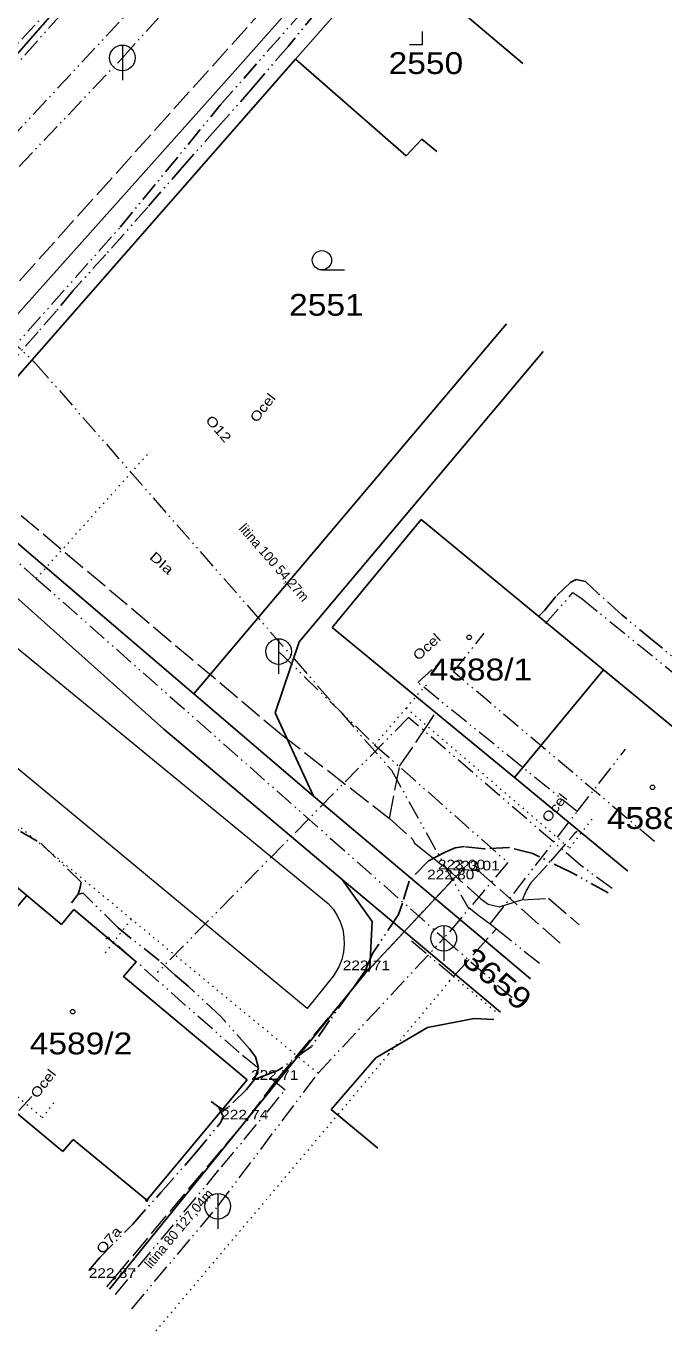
# Model space of a CAD drawing. Extents: x -683947 to -683762, y -1065756 to -1065543.
# Drawn here: x -683884.2 to -683834.4, y -1065755.7 to -1065654 of the extents above; entities that cross this region are included whole.
import ezdxf
from ezdxf.enums import TextEntityAlignment as Align

# ---------------------------------------------------------------- set-up
doc = ezdxf.new("R2010")
doc.units = 0
doc.header["$LTSCALE"] = 0.3
doc.header["$PDMODE"] = 32
doc.header["$PDSIZE"] = 0.15
for name, pattern in [('DASH_DOUBLE_DOT', [9.2, 5, -1.2, 0.3, -1.2, 0.3, -1.2]), ('DOTTED', [1.5, 0.3, -1.2]), ('LONG_DASHED', [7.5, 6, -1.5])]:
    doc.linetypes.add(name, pattern=pattern)
for name, color, linetype, lineweight in [('1', 7, 'Continuous', 25), ('10', 7, 'Continuous', 13), ('25', 7, 'Continuous', 13), ('3', 7, 'Continuous', 13), ('30', 7, 'LONG_DASHED', 13), ('31', 7, 'DASH_DOUBLE_DOT', 13), ('35', 7, 'LONG_DASHED', 13), ('36', 7, 'DASH_DOUBLE_DOT', 25), ('4', 7, 'Continuous', 13), ('41', 7, 'DASH_DOUBLE_DOT', 13), ('46', 7, 'DASH_DOUBLE_DOT', 13), ('5', 7, 'Continuous', 13), ('50', 7, 'LONG_DASHED', 13), ('51', 7, 'DOTTED', 13)]:
    doc.layers.add(name, color=color, linetype=linetype, lineweight=lineweight)
for name, color, linetype in [('15', 7, 'Continuous'), ('16', 7, 'Continuous'), ('19', 7, 'Continuous'), ('2', 7, 'Continuous')]:
    doc.layers.add(name, color=color, linetype=linetype)

msp = doc.modelspace()

# ---------------------------------------------------------------- linework, layer by layer
at = {"layer": '1'}
for p, q in [((-683867.65, -1065657.22), (-683844.35, -1065631.04)), ((-683863.13, -1065656.59), (-683855.75, -1065648.18)), ((-683845.419, -1065656.92), (-683855.75, -1065648.18)), ((-683888.65, -1065685.67), (-683863.13, -1065656.59)), ((-683863.13, -1065656.59), (-683854.52, -1065664.13)), ((-683886.11, -1065677.9), (-683867.65, -1065657.22)), ((-683854.52, -1065664.13), (-683853.28, -1065662.81)), ((-683853.28, -1065662.81), (-683852.122, -1065663.784)), ((-683846.693, -1065677.227), (-683871.07, -1065706.07)), ((-683843.823, -1065679.379), (-683862.85, -1065702.02)), ((-683886.97, -1065692.49), (-683871.07, -1065706.07)), ((-683860.28, -1065700.9), (-683853.33, -1065692.48)), ((-683853.33, -1065692.48), (-683839.13, -1065704.18)), ((-683890.08, -1065693.94), (-683873.4, -1065708.83)), ((-683846.07, -1065712.6), (-683860.28, -1065700.9)), ((-683862.85, -1065702.02), (-683864.72, -1065707.54)), ((-683846.07, -1065712.6), (-683839.13, -1065704.18)), ((-683839.13, -1065704.18), (-683829.912, -1065711.781)), ((-683871.07, -1065706.07), (-683861.75, -1065714.03)), ((-683864.72, -1065707.54), (-683861.75, -1065714.03)), ((-683873.4, -1065708.83), (-683859.51, -1065720.53)), ((-683837.223, -1065719.883), (-683846.07, -1065712.6)), ((-683861.75, -1065714.03), (-683844.81, -1065728.29)), ((-683859.51, -1065720.53), (-683847.158, -1065730.892)), ((-683884.1, -1065721.78), (-683881.4, -1065724.04)), ((-683880.43, -1065722.89), (-683881.4, -1065724.04)), ((-683857.34, -1065727.39), (-683877.651, -1065752.468)), ((-683852.84, -1065732.07), (-683849.22, -1065731.37)), ((-683849.22, -1065731.37), (-683847.665, -1065731.453)), ((-683881.3, -1065741.76), (-683892.92, -1065732.04)), ((-683856.88, -1065734.45), (-683852.84, -1065732.07)), ((-683860.35, -1065738.48), (-683856.88, -1065734.45)), ((-683866.92, -1065736.17), (-683874.74, -1065745.55)), ((-683860.35, -1065738.48), (-683856.71, -1065741.477)), ((-683880.49, -1065740.8), (-683881.3, -1065741.76)), ((-683874.74, -1065745.55), (-683880.49, -1065740.8))]:
    msp.add_line(p, q, dxfattribs=at)
for points in [[(-683859.58, -1065630.9), (-683875.3, -1065645.28), (-683888.43, -1065660.25), (-683897.91, -1065674.98), (-683898.51, -1065675.59)], [(-683890.26, -1065716.63), (-683884.1, -1065721.78), (-683892.92, -1065732.04)], [(-683859.51, -1065720.53), (-683857.17, -1065723.82), (-683857.34, -1065727.39)], [(-683866.92, -1065736.17), (-683876.55, -1065728.11), (-683875.58, -1065726.95), (-683880.43, -1065722.89)]]:
    msp.add_lwpolyline(points, dxfattribs=at)
for p in [(-683850.03, -1065719.75), (-683848.89, -1065719.83), (-683850.87, -1065720.53), (-683857.45, -1065727.61), (-683864.6, -1065736.16), (-683866.93, -1065739.25), (-683874.73, -1065745.55), (-683877.26, -1065751.6)]:
    msp.add_point(p, dxfattribs=at)
at = {"layer": '10'}
for p, q in [((-683876.643, -1065655.478), (-683876.643, -1065658.226)), ((-683864.461, -1065701.762), (-683864.461, -1065704.51)), ((-683851.577, -1065724.123), (-683851.577, -1065726.871)), ((-683869.206, -1065745.016), (-683869.206, -1065747.764))]:
    msp.add_line(p, q, dxfattribs=at)
for centre in [(-683876.643, -1065656.48), (-683864.461, -1065702.764), (-683851.577, -1065725.125), (-683869.206, -1065746.018)]:
    msp.add_circle(centre, 1, dxfattribs=at)
at = {"layer": '25'}
msp.add_line((-683850.884, -1065720.557), (-683857.417, -1065727.554), dxfattribs=at)
at = {"layer": '3'}
msp.add_line((-683861.082, -1065673.01), (-683859.332, -1065673.01), dxfattribs=at)
msp.add_lwpolyline([(-683854.24, -1065655.43), (-683853.24, -1065655.43), (-683853.24, -1065654.43)], dxfattribs=at)
msp.add_circle((-683861.082, -1065672.26), 0.75, dxfattribs=at)
at = {"layer": '30'}
msp.add_lwpolyline([(-683877.845, -1065752.294), (-683877.26, -1065751.6), (-683866.93, -1065739.25), (-683864.6, -1065736.16), (-683857.45, -1065727.61), (-683850.87, -1065720.53), (-683850.03, -1065719.75), (-683848.89, -1065719.83), (-683842.386, -1065725.603)], dxfattribs=at)
at = {"layer": '31'}
for points in [[(-683906.37, -1065683.43), (-683899.08, -1065675.36), (-683887.96, -1065660.41), (-683873.71, -1065644.44), (-683851.65, -1065622.08)], [(-683914.84, -1065689.19), (-683909.62, -1065682.86), (-683896.8, -1065669.54), (-683888.32, -1065659.06), (-683854.06, -1065622.89)], [(-683843.64, -1065700.59), (-683841.5, -1065698.17), (-683840.79, -1065698.66), (-683827.681, -1065709.309)], [(-683835.143, -1065717.578), (-683850.82, -1065704.35), (-683848.42, -1065701.33)], [(-683867.54, -1065734.03), (-683877.74, -1065725.03), (-683877.93, -1065725.19)], [(-683877.188, -1065752.885), (-683868.91, -1065742.95), (-683863.95, -1065736.96), (-683867.54, -1065734.03)]]:
    msp.add_lwpolyline(points, dxfattribs=at)
at = {"layer": '35'}
msp.add_line((-683850.814, -1065728.102), (-683847.469, -1065724.389), dxfattribs=at)
for points in [[(-683896.24, -1065687.55), (-683894.71, -1065685.72), (-683893.48, -1065684.13), (-683891.61, -1065681.955), (-683887.89, -1065677.63), (-683886.16, -1065675.53), (-683853.44, -1065639.1), (-683848.45, -1065633.59), (-683843.114, -1065627.22), (-683843.08, -1065627.18), (-683831.4, -1065614.21), (-683820.06, -1065601.41), (-683812.91, -1065593.55), (-683807.75, -1065587.62), (-683793.84, -1065572.21), (-683791.969, -1065570.179), (-683790.708, -1065568.809), (-683790.074, -1065568.129)], [(-683887.28, -1065689.61), (-683886.26, -1065690.7), (-683864.21, -1065709.26), (-683855.82, -1065715.78), (-683853.98, -1065717.41), (-683853.87, -1065717.71), (-683852.4, -1065718.86), (-683851.92, -1065719.26), (-683851.43, -1065719.6), (-683848.68, -1065722.04), (-683848.11, -1065722.47), (-683847.23, -1065722.66), (-683845.45, -1065722.12), (-683843.4, -1065722), (-683841.012, -1065724.081)]]:
    msp.add_lwpolyline(points, dxfattribs=at)
at = {"layer": '36', "lineweight": 13}
for p, q in [((-683891.662, -1065672.348), (-683883.388, -1065680.331)), ((-683847.469, -1065724.389), (-683843.876, -1065727.255)), ((-683850.814, -1065728.102), (-683854.244, -1065725.23))]:
    msp.add_line(p, q, dxfattribs=at)
at = {"layer": '36'}
for p, q in [((-683880.1, -1065721.68), (-683880.61, -1065722.37)), ((-683869.11, -1065738.29), (-683869.73, -1065737.86))]:
    msp.add_line(p, q, dxfattribs=at)
at = {"layer": '36', "linetype": 'DOTTED', "lineweight": 13}
for p, q in [((-683851.132, -1065728.477), (-683850.814, -1065728.102)), ((-683850.814, -1065728.102), (-683847.287, -1065731.035))]:
    msp.add_line(p, q, dxfattribs=at)
at = {"layer": '36', "lineweight": 13}
for points in [[(-683893.079, -1065671.05), (-683871.468, -1065647.886), (-683863.976, -1065639.798), (-683853.405, -1065628.437)], [(-683883.388, -1065680.331), (-683855.658, -1065712.024), (-683849.733, -1065722.644)], [(-683849.733, -1065722.644), (-683848.854, -1065723.341), (-683847.96, -1065723.998), (-683847.469, -1065724.389)]]:
    msp.add_lwpolyline(points, dxfattribs=at)
at = {"layer": '36'}
for points in [[(-683861.4, -1065652.77), (-683863.72, -1065655.58), (-683866.45, -1065658.77), (-683869.22, -1065661.92), (-683871.81, -1065664.82), (-683874.67, -1065668.11), (-683877.93, -1065671.8), (-683880.49, -1065674.63), (-683881.78, -1065676.2), (-683883.21, -1065677.83), (-683885.92, -1065680.91), (-683888.71, -1065684.04), (-683891.65, -1065687.67), (-683894.43, -1065691.13), (-683895.32, -1065692.06), (-683895.79, -1065692.2), (-683896.27, -1065692.12), (-683897.08, -1065691.84)], [(-683828.07, -1065708.5), (-683828.11, -1065707.94), (-683829.41, -1065706.7), (-683832.38, -1065704.28), (-683835.16, -1065701.99), (-683837.7, -1065699.9), (-683839.54, -1065698.24), (-683840.53, -1065697.3), (-683841.24, -1065697.16), (-683841.68, -1065697.36), (-683842.84, -1065698.47), (-683843.7, -1065699.53), (-683844.21, -1065700.05)], [(-683894.53, -1065710.88), (-683894.11, -1065710.62), (-683893.72, -1065710.81), (-683891.9, -1065711.74), (-683890.27, -1065713.01), (-683886.64, -1065715.22), (-683884.59, -1065716.8), (-683882.93, -1065717.78), (-683879.86, -1065720.75), (-683879.93, -1065721.17), (-683880.1, -1065721.68)], [(-683838.762, -1065721.588), (-683841.61, -1065719.99), (-683844.64, -1065718.52), (-683846.48, -1065718.05), (-683848.39, -1065718.14), (-683849.95, -1065717.98), (-683850.7, -1065718.07), (-683851.47, -1065718.41), (-683852.76, -1065719.08), (-683854.29, -1065720.66), (-683854.8, -1065722.38), (-683855.11, -1065723.27), (-683857.13, -1065726.3), (-683857.72, -1065727.65), (-683858.93, -1065729.38), (-683860.49, -1065731.54), (-683861.89, -1065733.55), (-683864.46, -1065735.41), (-683865.62, -1065735.84), (-683866.33, -1065736.13)], [(-683866.33, -1065736.13), (-683866.03, -1065735.22), (-683866.26, -1065734.36), (-683866.72, -1065733.75), (-683868.98, -1065731.2), (-683871.51, -1065728.86), (-683872.53, -1065728), (-683873.78, -1065726.86), (-683876.98, -1065724.31), (-683879.7, -1065721.61), (-683880.1, -1065721.68)], [(-683866.33, -1065736.13), (-683866.96, -1065736.91), (-683868.4, -1065738.31), (-683868.74, -1065738.49), (-683869.11, -1065738.29)], [(-683879.254, -1065751.024), (-683878.43, -1065750.05), (-683875.83, -1065747.4), (-683873.61, -1065744.92), (-683871.02, -1065741.96), (-683868.99, -1065739.5), (-683868.78, -1065739.02), (-683869.11, -1065738.29)]]:
    msp.add_lwpolyline(points, dxfattribs=at)
at = {"layer": '36', "linetype": 'DOTTED', "lineweight": 13}
msp.add_lwpolyline([(-683874.022, -1065755.735), (-683855.873, -1065734.165), (-683851.132, -1065728.477)], dxfattribs=at)
at = {"layer": '4'}
for p, q in [((-683892.15, -1065696.52), (-683860.6, -1065722.41)), ((-683862.22, -1065730.6), (-683896.78, -1065702.01)), ((-683860.18, -1065728.05), (-683862.22, -1065730.6))]:
    msp.add_line(p, q, dxfattribs=at)
msp.add_lwpolyline([(-683860.6, -1065722.41), (-683860.21, -1065722.86), (-683859.89, -1065723.35), (-683859.64, -1065723.89), (-683859.46, -1065724.45), (-683859.36, -1065725.03), (-683859.34, -1065725.62), (-683859.4, -1065726.21), (-683859.54, -1065726.79), (-683859.76, -1065727.34), (-683860.18, -1065728.05)], dxfattribs=at)
at = {"layer": '41'}
for p, q in [((-683838.455, -1065721.248), (-683840.889, -1065719.446)), ((-683883.719, -1065737.449), (-683888.487, -1065742.712))]:
    msp.add_line(p, q, dxfattribs=at)
at = {"layer": '41', "lineweight": 25}
msp.add_lwpolyline([(-683907.26, -1065705.67), (-683893.37, -1065687.98), (-683887.71, -1065681.96), (-683876.81, -1065669.67), (-683869.01, -1065660.17), (-683861.43, -1065651.54), (-683852.89, -1065642.04), (-683845.02, -1065633.03), (-683836.31, -1065623.45), (-683820.34, -1065605.7), (-683789.54, -1065571.05), (-683781.76, -1065562.31), (-683777.124, -1065557.504)], dxfattribs=at)
at = {"layer": '41'}
msp.add_lwpolyline([(-683840.889, -1065719.446), (-683854.319, -1065707.903), (-683873.919, -1065727.794)], dxfattribs=at)
at = {"layer": '46'}
for p, q in [((-683876.643, -1065656.48), (-683852.585, -1065629.704)), ((-683864.461, -1065702.764), (-683856.969, -1065710.032)), ((-683851.577, -1065725.125), (-683846.179, -1065729.807)), ((-683875.92, -1065754.026), (-683869.206, -1065746.018))]:
    msp.add_line(p, q, dxfattribs=at)
for points in [[(-683899.015, -1065681.258), (-683890.444, -1065670.977), (-683876.643, -1065656.48)], [(-683896.766, -1065685.158), (-683883.356, -1065697.074), (-683851.577, -1065725.125)], [(-683856.969, -1065710.032), (-683846.574, -1065719.227), (-683851.577, -1065725.125)], [(-683869.206, -1065746.018), (-683861.384, -1065735.651), (-683851.577, -1065725.125)]]:
    msp.add_lwpolyline(points, dxfattribs=at)
at = {"layer": '5'}
for centre in [(-683849.597, -1065701.659), (-683835.297, -1065713.349), (-683880.517, -1065730.849)]:
    msp.add_circle(centre, 0.175, dxfattribs=at)
at = {"layer": '50'}
msp.add_line((-683852.75, -1065708.36), (-683852.32, -1065707.7), dxfattribs=at)
for points in [[(-683855.82, -1065715.78), (-683855.02, -1065711.7), (-683853.75, -1065709.86), (-683852.75, -1065708.36)], [(-683841.42, -1065717), (-683841.29, -1065716.85), (-683841.18, -1065716.77)], [(-683845.45, -1065722.12), (-683845.14, -1065721.44), (-683844.73, -1065720.76), (-683843.23, -1065719.12), (-683841.8, -1065717.44), (-683841.42, -1065717)]]:
    msp.add_lwpolyline(points, dxfattribs=at)
at = {"layer": '51'}
for p, q in [((-683883.356, -1065697.074), (-683874.494, -1065687.184)), ((-683854.503, -1065707.171), (-683852.709, -1065705.09)), ((-683856.969, -1065710.032), (-683854.503, -1065707.171))]:
    msp.add_line(p, q, dxfattribs=at)
at = {"layer": '51', "linetype": 'DASH_DOUBLE_DOT'}
for points in [[(-683841.173, -1065715.251), (-683853.596, -1065705.182), (-683851.899, -1065703.616)], [(-683847.96, -1065723.998), (-683847.821, -1065723.832), (-683841.173, -1065715.251), (-683837.417, -1065710.389)]]:
    msp.add_lwpolyline(points, dxfattribs=at)
at = {"layer": '51'}
for points in [[(-683854.503, -1065707.171), (-683841.765, -1065718.092), (-683839.938, -1065715.765)], [(-683875.957, -1065723.621), (-683890.608, -1065711.528), (-683893.1, -1065714.852)], [(-683905.808, -1065719.58), (-683882.889, -1065739.117), (-683881.78, -1065737.682)], [(-683861.384, -1065735.651), (-683875.957, -1065723.621), (-683878.148, -1065726.484)]]:
    msp.add_lwpolyline(points, dxfattribs=at)

# ---------------------------------------------------------------- texts
at = {"layer": '15', "width": 1.3}
msp.add_text('DIa', height=0.75, rotation=318.57, dxfattribs=at).set_placement((-683874.587, -1065695.477))
at = {"layer": '16', "width": 1.25}
for s, rotation, p in [('O12', 311.18, (-683870.21, -1065684.761)), ('O7a', 49.92, (-683878.182, -1065749.806))]:
    msp.add_text(s, height=0.75, rotation=rotation, dxfattribs=at).set_placement(p)
at = {"layer": '16'}
for s, rotation, p in [('litina 100 54,27m', 311.18, (-683867.61, -1065693.199)), ('litina 80 127,04m', 49.92, (-683874.424, -1065750.93))]:
    msp.add_text(s, height=0.75, rotation=rotation, dxfattribs=at).set_placement(p)
at = {"layer": '19', "width": 1.2}
for rotation, p in [(52.04, (-683866.165, -1065684.968)), (42.7, (-683853.561, -1065703.516)), (52.31, (-683843.399, -1065716.169)), (52.3, (-683883.284, -1065737.664))]:
    msp.add_text('Ocel ', height=0.75, rotation=rotation, dxfattribs=at).set_placement(p)
at = {"layer": '2', "width": 1.15}
for s, p in [('2550', (-683855.88, -1065657.74)), ('2551', (-683863.64, -1065676.58)), ('4588/1', (-683852.68, -1065705.02)), ('4588/2', (-683838.86, -1065716.6)), ('4589/2', (-683883.87, -1065734.17))]:
    msp.add_text(s, height=1.7, dxfattribs=at).set_placement(p)
at = {"layer": '2', "width": 1.2}
msp.add_text('3659', height=1.7, rotation=320.075, dxfattribs=at).set_placement((-683850.29, -1065726.99))
at = {"layer": '3', "width": 1.2}
for s, p in [('222 80 ', (-683850.87, -1065720.53)), ('223 00 ', (-683850.03, -1065719.75)), ('223 01 ', (-683848.89, -1065719.83)), ('222 71 ', (-683857.45, -1065727.61)), ('222 71 ', (-683864.6, -1065736.16)), ('222 74 ', (-683866.93, -1065739.25)), ('222 87 ', (-683877.26, -1065751.6))]:
    msp.add_text(s, height=0.75, dxfattribs=at).set_placement(p, align=Align.CENTER)

doc.saveas('drawing.dxf')
